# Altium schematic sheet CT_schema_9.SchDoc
size 277 x 170 mm
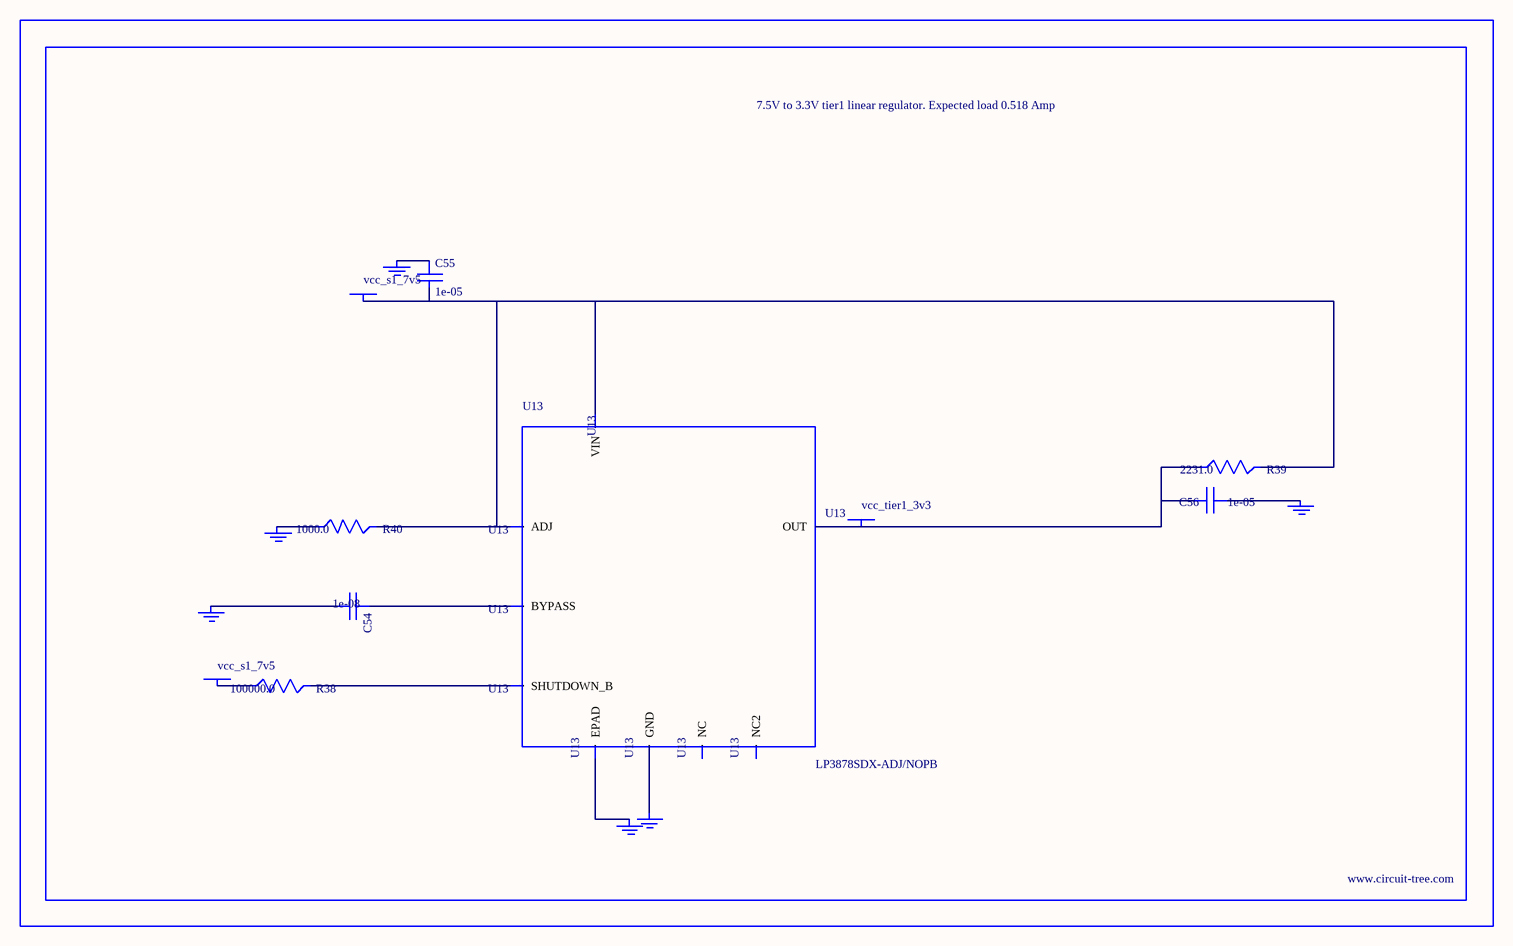
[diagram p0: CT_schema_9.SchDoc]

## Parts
BORDER8  (no value)
C54  1e-08  [C0402]
C55  1e-05  [C1206]
C56  1e-05  [C1210]
GND_INSTANCE_8_0  (no value)
GND_INSTANCE_8_1  (no value)
GND_INSTANCE_8_2  (no value)
GND_INSTANCE_8_3  (no value)
GND_INSTANCE_8_4  (no value)
GND_INSTANCE_8_5  (no value)
POWER_INSTANCE_8_0  vcc_s1_7v5
POWER_INSTANCE_8_1  vcc_s1_7v5
POWER_INSTANCE_8_2  vcc_tier1_3v3
R38  100000.0  [R0603]
R39  2231.0  [R0603]
R40  1000.0  [R0603]
U13  LP3878SDX-ADJ/NOPB  [WSON-8]

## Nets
NetC54_1: C54.1 U13.1(BYPASS)
NetC54_2: C54.2 GND_INSTANCE_8_0.0(GND)
NetC55_1: C55.1 GND_INSTANCE_8_1.0(GND)
NetC55_2: C55.2 POWER_INSTANCE_8_0.0(PWR) R39.2 R40.2 U13.4(VIN) U13.6(ADJ)
NetC56_1: C56.1 GND_INSTANCE_8_2.0(GND)
NetC56_2: C56.2 POWER_INSTANCE_8_2.0(PWR) R39.1 U13.5(OUT)
NetGND_INSTANCE_8_3_0: GND_INSTANCE_8_3.0(GND) R40.1
NetGND_INSTANCE_8_4_0: GND_INSTANCE_8_4.0(GND) U13.PAD(EPAD)
NetGND_INSTANCE_8_5_0: GND_INSTANCE_8_5.0(GND) U13.3(GND)
NetPOWER_INSTANCE_8_1_0: POWER_INSTANCE_8_1.0(PWR) R38.1
NetR38_2: R38.2 U13.8(SHUTDOWN_B)

Not connected (* = marked no-connect by the designer): U13 2(NC) 7(NC2)

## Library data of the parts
BORDER8 = BORDER_PAGE8
C54 = C0402C103K3RAC
C55 = C1206C106K3RACTU
C56 = GRM32DR61E106MA12L
GND_INSTANCE_8_0-GND_INSTANCE_8_5 = GND
POWER_INSTANCE_8_0-POWER_INSTANCE_8_2 = PWR
R38 = RC0603JR-07100KL
R39 = R39
R40 = RC0603JR-071KL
